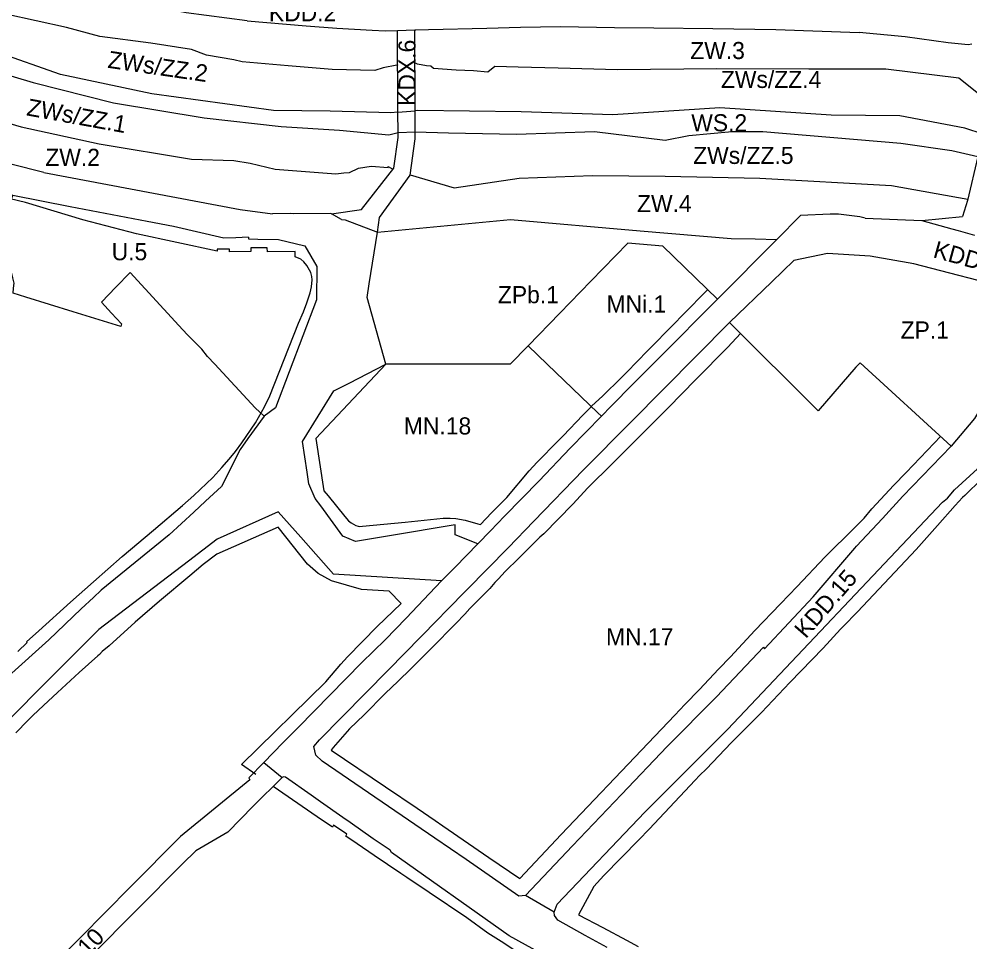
# Model space of a CAD drawing. Extents: x 7418991 to 7423142, y 5547704 to 5549547.
# Drawn here: x 7420035 to 7420312.9, y 5548281.5 to 5548551.2 of the extents above; entities that cross this region are included whole.
import ezdxf

# ---------------------------------------------------------------- set-up
doc = ezdxf.new("R2010")
doc.units = 0
for name, color, linetype in [('LIN_Linia Zabudowy Nieprzekraczalna', 7, 'Continuous'), ('LIN_linie_rozgraniczajace', 7, 'Continuous'), ('LIN_Orientacyjny przebieg terenow WS pod terenami komunikacyjnymi', 7, 'Continuous'), ('TXT_Oznaczenia_przeznaczen', 7, 'Continuous')]:
    doc.layers.add(name, color=color, linetype=linetype)

msp = doc.modelspace()

# ---------------------------------------------------------------- linework, layer by layer
at = {"layer": 'LIN_Linia Zabudowy Nieprzekraczalna'}
msp.add_line((7420172.32, 5548306.13), (7420181.35, 5548300.06), dxfattribs=at)
for points in [[(7420034.6, 5548366.36), (7420037.35, 5548369.05), (7420037.21, 5548369.21), (7420040.73, 5548372.45), (7420050.02, 5548380.77), (7420056.73, 5548386.74), (7420065.17, 5548394.09), (7420074.32, 5548401.81), (7420082.77, 5548409.02), (7420086.09, 5548411.99), (7420091.62, 5548417.27), (7420094.28, 5548420.12), (7420096.42, 5548422.55), (7420098.27, 5548424.78), (7420100.09, 5548427.35), (7420104.05, 5548433.22), (7420106.73, 5548437.9), (7420108.27, 5548441.11), (7420116.67, 5548462.31), (7420118.1, 5548465.62), (7420119.13, 5548468.25), (7420120.06, 5548471.15), (7420120.46, 5548472.96), (7420120.67, 5548475.04), (7420120.6, 5548475.97), (7420120.25, 5548477.15), (7420119.14, 5548479.15), (7420118.24, 5548480.24), (7420117.37, 5548480.99), (7420116.9, 5548481.24), (7420115.67, 5548481.73), (7420115.66, 5548483.24), (7420107.59, 5548483.15), (7420107.55, 5548484.38), (7420104.25, 5548484.33), (7420102.7, 5548484.32), (7420102.76, 5548483.24), (7420096.52, 5548483.14), (7420096.52, 5548483.96), (7420092.91, 5548483.99), (7420092.92, 5548483.37), (7420069.34, 5548488.4), (7420053.58, 5548492.52), (7420036.89, 5548497.59), (7420029.91, 5548499.2)], [(7420142.23, 5548450.36), (7420121.77, 5548428.59), (7420121.77, 5548428.59), (7420124.11, 5548413.36), (7420125.33, 5548411.91), (7420130.18, 5548405.78), (7420131.28, 5548404.6), (7420132.07, 5548404.01), (7420133.4, 5548403.21), (7420134.11, 5548402.98), (7420134.49, 5548402.93), (7420135.33, 5548402.96), (7420147.82, 5548404.19), (7420158.95, 5548405.36), (7420161.04, 5548405.38), (7420162.69, 5548405.24), (7420165.34, 5548404.74), (7420169.08, 5548403.69), (7420169.85, 5548403.53), (7420173.07, 5548406.85), (7420177.52, 5548411.39), (7420184.05, 5548419.18), (7420186.42, 5548421.66), (7420192.54, 5548427.94), (7420193.99, 5548429.38), (7420199.81, 5548435.41), (7420202.26, 5548437.95), (7420202.34, 5548438.03), (7420204.58, 5548440.12), (7420205.53, 5548441), (7420211.03, 5548446.48), (7420212.59, 5548448.05), (7420218.72, 5548454.29), (7420221.06, 5548456.67), (7420224.09, 5548459.75), (7420225.22, 5548460.91), (7420235.18, 5548470.99), (7420236.27, 5548472.16)], [(7420245.86, 5548459.33), (7420242.12, 5548455.28), (7420232.81, 5548445.85), (7420224.7, 5548437.61), (7420216.85, 5548429.65), (7420215.56, 5548428.45), (7420212.44, 5548425.28), (7420208.46, 5548421.29), (7420201.26, 5548414.16), (7420196.88, 5548409.41), (7420188.34, 5548400.8), (7420187.19, 5548399.8), (7420186.13, 5548398.69), (7420181.11, 5548393.66), (7420177.11, 5548389.72)], [(7420284.24, 5548408.09), (7420286.9, 5548410.88), (7420290.61, 5548414.84), (7420294.24, 5548418.69), (7420302.48, 5548427.22), (7420304.36, 5548429.2)], [(7420316.37, 5548416.85), (7420311.47, 5548411.98), (7420310.73, 5548411.34), (7420308.59, 5548409.07), (7420303.4, 5548403.15), (7420297.23, 5548396.17), (7420280.01, 5548377.98), (7420275.88, 5548373.7), (7420275.09, 5548372.88), (7420269.98, 5548367.33), (7420260.23, 5548357.33), (7420251.95, 5548348.56), (7420243.13, 5548339.7), (7420235.91, 5548332.11), (7420233.87, 5548330.09), (7420232.62, 5548328.74), (7420219.13, 5548314.46), (7420216.16, 5548311.33), (7420205.91, 5548300.89), (7420202.96, 5548297.7), (7420198.53, 5548289.43), (7420205.61, 5548285.67), (7420212.5, 5548282.01), (7420215.9, 5548280.19)], [(7420181.35, 5548300.06), (7420193.47, 5548312.92), (7420218.87, 5548339.54), (7420226.65, 5548347.8), (7420229.62, 5548350.91), (7420233.86, 5548355.31), (7420239.42, 5548361.21), (7420242.92, 5548364.83), (7420250.09, 5548372.52), (7420257.56, 5548380.29), (7420262.39, 5548385.33), (7420270.46, 5548393.92), (7420279.23, 5548402.63), (7420282.05, 5548405.34), (7420284.24, 5548408.09)], [(7420104.17, 5548330.46), (7420099.98, 5548333.37), (7420124.64, 5548357.54), (7420129, 5548362.69), (7420131.03, 5548364.77), (7420139.63, 5548373.63), (7420146.65, 5548380.36), (7420143.2, 5548383.97), (7420135.06, 5548384.46), (7420126.3, 5548386.98), (7420122.42, 5548389.21), (7420119.34, 5548391.92), (7420110.68, 5548402.74), (7420092.79, 5548394.8), (7420088.84, 5548391.79), (7420084.86, 5548388.5), (7420076.06, 5548381.07), (7420068.97, 5548374.91), (7420061.28, 5548368.07), (7420059.3, 5548366.33), (7420058.49, 5548365.52), (7420057.99, 5548365.06), (7420052.57, 5548360.25), (7420046.23, 5548354.41), (7420042.13, 5548350.63), (7420039.01, 5548347.62), (7420037.56, 5548346.25), (7420034.04, 5548342.63)], [(7420177.11, 5548389.72), (7420175.12, 5548387.6), (7420174.03, 5548386.5), (7420172.57, 5548384.8), (7420168.53, 5548380.7), (7420167.57, 5548379.7), (7420166.77, 5548378.98), (7420165.24, 5548377.25), (7420162.61, 5548374.6), (7420160.49, 5548372.45), (7420157.65, 5548369.45), (7420149.5, 5548361.27), (7420145.82, 5548357.74), (7420141.99, 5548354.06), (7420135.86, 5548347.87), (7420131.6, 5548343.73), (7420126.8, 5548338.28), (7420126.25, 5548337.57)], [(7420126.25, 5548337.57), (7420142.06, 5548326.8), (7420151.31, 5548320.57), (7420156.61, 5548316.94), (7420158.81, 5548315.39), (7420172.32, 5548306.13)], [(7420126.58, 5548315.07), (7420122.08, 5548318.02), (7420109.24, 5548326.94)], [(7420130.49, 5548312.44), (7420130.83, 5548312.98), (7420126.89, 5548315.57), (7420126.58, 5548315.07)], [(7420171.96, 5548284.09), (7420165.88, 5548288.49), (7420154.89, 5548295.92), (7420148.36, 5548300.37), (7420146.54, 5548301.51), (7420138.81, 5548306.73), (7420133.83, 5548310.12), (7420130.49, 5548312.44)], [(7420237.78, 5548247.63), (7420224.14, 5548255.15), (7420214.05, 5548260.52), (7420213.07, 5548261.03), (7420207.42, 5548264.13), (7420205.33, 5548265.07), (7420204.63, 5548265.38), (7420201.48, 5548267.03), (7420194.08, 5548270.96), (7420191.28, 5548272.61), (7420181.08, 5548278.29), (7420180.07, 5548278.89), (7420179.13, 5548279.52), (7420176.65, 5548281.16), (7420171.96, 5548284.09)]]:
    msp.add_lwpolyline(points, dxfattribs=at)
at = {"layer": 'LIN_linie_rozgraniczajace'}
for p, q in [((7420048.85, 5548548.76), (7420031.14, 5548552.63)), ((7420058.61, 5548546.09), (7420048.85, 5548548.76)), ((7420073.48, 5548544.19), (7420058.61, 5548546.09)), ((7420256.22, 5548548.13), (7420280.58, 5548547.3)), ((7420085.39, 5548542.31), (7420073.48, 5548544.19)), ((7420089.74, 5548540.69), (7420085.39, 5548542.31)), ((7420097.8, 5548539.27), (7420089.74, 5548540.69)), ((7420100.24, 5548538.67), (7420097.8, 5548539.27)), ((7420113.66, 5548537.58), (7420100.24, 5548538.67)), ((7420126.47, 5548536.45), (7420113.66, 5548537.58)), ((7420145.45, 5548537.7), (7420141.43, 5548536.93)), ((7420145.67, 5548537.86), (7420145.45, 5548537.7)), ((7420150.83, 5548538.29), (7420150.67, 5548538.31)), ((7420151.45, 5548538.02), (7420150.83, 5548538.29)), ((7420154.1, 5548537.5), (7420151.45, 5548538.02)), ((7420155.31, 5548537.39), (7420154.1, 5548537.5)), ((7420156.16, 5548536.78), (7420155.31, 5548537.39)), ((7420174.09, 5548537.34), (7420171.99, 5548535.73)), ((7420180.9, 5548537.15), (7420174.09, 5548537.34)), ((7420192.52, 5548536.87), (7420180.9, 5548537.15)), ((7420138.96, 5548536.2), (7420126.47, 5548536.45)), ((7420141.43, 5548536.93), (7420138.96, 5548536.2)), ((7420162.74, 5548536.27), (7420156.16, 5548536.78)), ((7420167.79, 5548536.06), (7420162.74, 5548536.27)), ((7420171.99, 5548535.73), (7420167.79, 5548536.06)), ((7420209.87, 5548536.39), (7420192.52, 5548536.87)), ((7420238.96, 5548536.67), (7420209.87, 5548536.39)), ((7420265.81, 5548536.6), (7420238.96, 5548536.67)), ((7420288.31, 5548536.52), (7420265.81, 5548536.6)), ((7420309.63, 5548533.94), (7420288.31, 5548536.52)), ((7420317.9, 5548527.42), (7420309.63, 5548533.94)), ((7420016.69, 5548525.28), (7420035.64, 5548519.71)), ((7420035.64, 5548519.71), (7420058.42, 5548514.75)), ((7420058.42, 5548514.75), (7420085.38, 5548510.26)), ((7420085.38, 5548510.26), (7420097.72, 5548509.85)), ((7420097.72, 5548509.85), (7420102.55, 5548509.13)), ((7420042.19, 5548506.4), (7420032.55, 5548508.76)), ((7420102.55, 5548509.13), (7420109.87, 5548507.31)), ((7420109.87, 5548507.31), (7420127.57, 5548505.95)), ((7420131.58, 5548506.33), (7420134.23, 5548507.65)), ((7420134.23, 5548507.65), (7420137.95, 5548508.21)), ((7420137.95, 5548508.21), (7420142.88, 5548507.82)), ((7420142.88, 5548507.82), (7420142.9, 5548508.07)), ((7420142.9, 5548508.07), (7420144.28, 5548507.29)), ((7420127.57, 5548505.95), (7420129.95, 5548506.22)), ((7420129.95, 5548506.22), (7420131.58, 5548506.33)), ((7420149.33, 5548505.72), (7420162.17, 5548501.92)), ((7420162.17, 5548501.92), (7420181.12, 5548504.67)), ((7420181.12, 5548504.67), (7420202.56, 5548505.44)), ((7420202.56, 5548505.44), (7420223.82, 5548505.27)), ((7420223.82, 5548505.27), (7420251.53, 5548504.67)), ((7420251.53, 5548504.67), (7420289.97, 5548502.56)), ((7420289.97, 5548502.56), (7420312.35, 5548498.6)), ((7420298.88, 5548492.32), (7420310.79, 5548493.54)), ((7420223.18, 5548484.8), (7420212.97, 5548485.68)), ((7420223.18, 5548484.8), (7420239.14, 5548469.39)), ((7420104, 5548437.58), (7420106.67, 5548435.18)), ((7420106.67, 5548435.18), (7420101.88, 5548428.64)), ((7420158.48, 5548387.04), (7420154.98, 5548383.32)), ((7420106.51, 5548333.93), (7420111.91, 5548329.57)), ((7420178.28, 5548283.31), (7420143.89, 5548307.63))]:
    msp.add_line(p, q, dxfattribs=at)
for points in [[(7420073.76, 5548529.37), (7420047.08, 5548535), (7420028.23, 5548541.62), (7420003.67, 5548548.84), (7419981.84, 5548558.41), (7419945.29, 5548578.67), (7419918.24, 5548595.43), (7419880.08, 5548624.72)], [(7420101.65, 5548550.71), (7420083.87, 5548553.03), (7420081.26, 5548553.53)], [(7420101.65, 5548550.71), (7420118.9, 5548549.2), (7420127.9, 5548548.5), (7420138.22, 5548548), (7420141.97, 5548547.78), (7420145.63, 5548547.9), (7420150.63, 5548548.02), (7420150.98, 5548548.03), (7420154.65, 5548548.14)], [(7420154.65, 5548548.14), (7420171.74, 5548548.5), (7420181.51, 5548548.83), (7420193.29, 5548549.01), (7420209.01, 5548548.75), (7420220.52, 5548548.6), (7420237.78, 5548548.43), (7420256.22, 5548548.13)], [(7420126.35, 5548494.25), (7420135.04, 5548495.54), (7420144.54, 5548507.63), (7420145.75, 5548516.54), (7420145.75, 5548518.05), (7420145.72, 5548523.96), (7420145.63, 5548547.9)], [(7420139.8, 5548488.92), (7420140.31, 5548493.18), (7420149.31, 5548505.61), (7420150.75, 5548516.21), (7420150.75, 5548518.2), (7420150.72, 5548524.39), (7420150.63, 5548548.02)], [(7420313.51, 5548543.89), (7420312.43, 5548543.71), (7420306.53, 5548544.23), (7420293.98, 5548546.02), (7420280.58, 5548547.3)], [(7420013.19, 5548540.38), (7420039.08, 5548532.71), (7420062.63, 5548526.75), (7420089.13, 5548522.35), (7420111.61, 5548519.84)], [(7420322.75, 5548541.8), (7420319.18, 5548527.65), (7420316.8, 5548517.55), (7420315.27, 5548511.05), (7420312.24, 5548498.16), (7420310.79, 5548493.54)], [(7420145.72, 5548523.96), (7420143.7, 5548523.79), (7420125.92, 5548524.26), (7420109.34, 5548524.44), (7420073.76, 5548529.37)], [(7420316.8, 5548517.55), (7420311.39, 5548519.28), (7420292.38, 5548522.88), (7420272.31, 5548523.1), (7420239.8, 5548525.23), (7420208.56, 5548523.24), (7420181.75, 5548524.11), (7420151.53, 5548524.46), (7420150.72, 5548524.39)], [(7420111.61, 5548519.84), (7420128.64, 5548518.76), (7420143.04, 5548517.32), (7420145.75, 5548518.05)], [(7420150.75, 5548518.2), (7420160.53, 5548517.95), (7420180.36, 5548517.54)], [(7420180.36, 5548517.54), (7420203.18, 5548518.38), (7420223.79, 5548515.78), (7420230.78, 5548517.2), (7420243.46, 5548518.36), (7420252.36, 5548518.3), (7420292.72, 5548514.97), (7420307.65, 5548512.78), (7420315.27, 5548511.05)], [(7420042.19, 5548506.4), (7420099.65, 5548495.51), (7420109.11, 5548494.27)], [(7420102.05, 5548487.44), (7420098.3, 5548487.29), (7420094.85, 5548487.14), (7420080.12, 5548490.58), (7420072.4, 5548492), (7420049.93, 5548496.37), (7420033.21, 5548499.61), (7420032.5, 5548499.98), (7420031.64, 5548500.52), (7420028.77, 5548502.25), (7420028.02, 5548502.66)], [(7420059.04, 5548468.48), (7420061.98, 5548465.29), (7420064.91, 5548462.09), (7420064.8, 5548461.72), (7420064.7, 5548461.35), (7420050.83, 5548465.66), (7420036.97, 5548469.97), (7420033.31, 5548471.11), (7420033.41, 5548472.58), (7420033.51, 5548474.05), (7420033.15, 5548475.53), (7420032.78, 5548477), (7420030.7, 5548480.41), (7420028.62, 5548483.81), (7420027.7, 5548485.84), (7420030.46, 5548492.73), (7420033.21, 5548499.61)], [(7420129.19, 5548492.6), (7420126.35, 5548494.25), (7420126.13, 5548494.38), (7420115.27, 5548494.26), (7420114.31, 5548494.39), (7420109.11, 5548494.27)], [(7420129.19, 5548492.6), (7420130.34, 5548492.53), (7420139.8, 5548488.92)], [(7420139.8, 5548488.92), (7420178.62, 5548492.62), (7420216.55, 5548489.36), (7420243.12, 5548487.07), (7420250.16, 5548486.93), (7420256.45, 5548486.81)], [(7420256.45, 5548486.81), (7420263.44, 5548493.84)], [(7420282.26, 5548493.03), (7420280.7, 5548493.36), (7420274.48, 5548494.15), (7420272.04, 5548494.22), (7420263.44, 5548493.84)], [(7420282.26, 5548493.03), (7420298.88, 5548492.32), (7420307.66, 5548489.91), (7420309.48, 5548489.39), (7420314.29, 5548488.01)], [(7420102.05, 5548487.44), (7420102.07, 5548486.98), (7420104.77, 5548486.92), (7420110.82, 5548486.78), (7420118.5, 5548484.88), (7420122.02, 5548478.85), (7420121.94, 5548469.19), (7420109.97, 5548437.61), (7420106.67, 5548435.18)], [(7420205.18, 5548435.14), (7420204.13, 5548436.15), (7420189.35, 5548450.34), (7420183.76, 5548455.71), (7420178.53, 5548450.35), (7420142.23, 5548450.36), (7420136.72, 5548469.87), (7420137.36, 5548473.85), (7420139.8, 5548488.92)], [(7420183.76, 5548455.71), (7420193.08, 5548465.27), (7420202.13, 5548474.56), (7420212.97, 5548485.68)], [(7420256.45, 5548486.81), (7420239.14, 5548469.39), (7420237.44, 5548467.68)], [(7420330.47, 5548470.16), (7420327.57, 5548471.58), (7420325.85, 5548472.03), (7420296.52, 5548479.65), (7420283.8, 5548481.93), (7420271.25, 5548482.64), (7420261.45, 5548480.64), (7420254.99, 5548474.39), (7420242.67, 5548462.51)], [(7420104, 5548437.58), (7420092.17, 5548450.39), (7420090.1, 5548452.63), (7420088.39, 5548454.7), (7420084.13, 5548458.97), (7420081.69, 5548461.62), (7420067.48, 5548477.11), (7420063.26, 5548472.8), (7420059.04, 5548468.48)], [(7420237.44, 5548467.68), (7420223.7, 5548453.86), (7420214.51, 5548444.61), (7420208.04, 5548438.1), (7420205.18, 5548435.14), (7420196.11, 5548425.75), (7420186.97, 5548416.28), (7420176.92, 5548405.88), (7420172.8, 5548401.66), (7420169.05, 5548397.82), (7420162.42, 5548391.04), (7420158.48, 5548387.04)], [(7420191.37, 5548290.16), (7420192.24, 5548292.52), (7420217.89, 5548319.42), (7420242.02, 5548343.53), (7420304.85, 5548409.98), (7420306.38, 5548411.15), (7420308.4, 5548413.59), (7420315.16, 5548419.76), (7420321.32, 5548427.36), (7420324.56, 5548432.31), (7420326.3, 5548434.96), (7420331.4, 5548445.41), (7420341.19, 5548465.32), (7420343.42, 5548470.14)], [(7420328.33, 5548465.17), (7420322.86, 5548452.47), (7420317.05, 5548439.23), (7420314.25, 5548434.48), (7420307.45, 5548426.37), (7420280.85, 5548450.7), (7420279.61, 5548449.42), (7420268.58, 5548436.74), (7420242.67, 5548462.51)], [(7420121.18, 5548338.57), (7420122.8, 5548340.59), (7420142.89, 5548360.94), (7420157.33, 5548375.66), (7420159.94, 5548378.32), (7420171.94, 5548390.52), (7420177.92, 5548396.69), (7420185.49, 5548404.49), (7420200.01, 5548419.46), (7420213.82, 5548433.39), (7420242.67, 5548462.51)], [(7420169.05, 5548397.82), (7420162.46, 5548400.47), (7420162.47, 5548403.41), (7420143.24, 5548400.2), (7420133.31, 5548398.54), (7420129.65, 5548400.06), (7420123.17, 5548408.9), (7420121.55, 5548411.12), (7420119.71, 5548415.42), (7420119.23, 5548418.77), (7420117.85, 5548427.78), (7420127.01, 5548442.57), (7420131.43, 5548444.83), (7420142.23, 5548450.36)], [(7420101.88, 5548428.64), (7420099.58, 5548425.39), (7420094.14, 5548414.63), (7420089.44, 5548410.27), (7420086.07, 5548407.13), (7420078.82, 5548400.46), (7420059, 5548384.29), (7420056.7, 5548382.17), (7420053.1, 5548378.85), (7420043.71, 5548369.75), (7420031.87, 5548359.17), (7420023.15, 5548351.99), (7420013.93, 5548342.29), (7420003.1, 5548330.8)], [(7420183, 5548295.08), (7420196.74, 5548309.57), (7420211.1, 5548324.59), (7420224.43, 5548338.64), (7420238.85, 5548353.12), (7420252.54, 5548367.59), (7420252.91, 5548367.19), (7420267.07, 5548382.36), (7420279.28, 5548396.58), (7420279.8, 5548397.13), (7420287.36, 5548405.2), (7420293.34, 5548411.78), (7420307.45, 5548426.37)], [(7420158.48, 5548387.04), (7420126.91, 5548388.97), (7420117.31, 5548399.77), (7420110.75, 5548407.15), (7420092.89, 5548399.22), (7420084.49, 5548392.8), (7420058.27, 5548372.81), (7420044.54, 5548359.06), (7420016.1, 5548330.54), (7420017.89, 5548328.64), (7419997.32, 5548306.91), (7419972.24, 5548279.73), (7419955.89, 5548261.61), (7419938.28, 5548242.93), (7419917.3, 5548219.73), (7419911.59, 5548213.29), (7419908.65, 5548209.49)], [(7420154.98, 5548383.32), (7420148.16, 5548376.08), (7420141.98, 5548369.82), (7420135.19, 5548363.15), (7420116.58, 5548344.18), (7420112.13, 5548339.67), (7420106.51, 5548333.93)], [(7420206.86, 5548279.87), (7420200.41, 5548283.37), (7420192.46, 5548287.89), (7420191.53, 5548289.19), (7420191.37, 5548290.16), (7420183, 5548295.08), (7420181.1, 5548294.91), (7420165.65, 5548305.61), (7420156.47, 5548311.85), (7420123.56, 5548334.3), (7420121.71, 5548336.11), (7420121.18, 5548338.57)], [(7420106.51, 5548333.93), (7420102.14, 5548329.46), (7420102.47, 5548328.89)], [(7420111.92, 5548329.58), (7420111.91, 5548329.57), (7420103.38, 5548321.17), (7420095.97, 5548313.59), (7420086.63, 5548308.14), (7420082.78, 5548304.28), (7420069.37, 5548290.83), (7420055.95, 5548277.38), (7420050.3, 5548271.71), (7420050.35, 5548267.51), (7420043.99, 5548261.14), (7420039.67, 5548265.29), (7420037.82, 5548266.71), (7420035.28, 5548269.12), (7420041.67, 5548275.57), (7420045.88, 5548275.57), (7420052.97, 5548282.76), (7420067.6, 5548297.55), (7420082.18, 5548312.32)], [(7420102.47, 5548328.89), (7420082.18, 5548312.32)], [(7420143.89, 5548307.63), (7420143.48, 5548308.28), (7420138.53, 5548311.65), (7420131.76, 5548316.37), (7420129.64, 5548317.85), (7420123.13, 5548322.46), (7420120.34, 5548324.4), (7420112.83, 5548329.69), (7420112.28, 5548329.71), (7420111.92, 5548329.58)], [(7420212.54, 5548264.35), (7420178.28, 5548283.31)]]:
    msp.add_lwpolyline(points, dxfattribs=at)
at = {"layer": 'LIN_Orientacyjny przebieg terenow WS pod terenami komunikacyjnymi'}
for p, q in [((7420145.72, 5548523.96), (7420150.72, 5548524.39)), ((7420145.75, 5548518.05), (7420150.75, 5548518.2))]:
    msp.add_line(p, q, dxfattribs=at)

# ---------------------------------------------------------------- texts
at = {"layer": 'TXT_Oznaczenia_przeznaczen'}
for s, p in [('KDD.2', (7420108.02, 5548550.54)), ('ZW.3', (7420231.17, 5548539.51)), ('ZWs/ZZ.4', (7420240.13, 5548531.07)), ('ZW.2', (7420042.66, 5548508.28)), ('ZWs/ZZ.5', (7420232.02, 5548508.86)), ('ZW.4', (7420215.62, 5548494.77)), ('U.5', (7420062.05, 5548480.71)), ('ZPb.1', (7420174.94, 5548468.16)), ('MNi.1', (7420206.7, 5548465.43)), ('ZP.1', (7420292.66, 5548457.83)), ('MN.18', (7420147.45, 5548429.8)), ('MN.17', (7420206.55, 5548368.19))]:
    msp.add_text(s, height=5, dxfattribs=at).set_placement(p)
for s, rotation, p in [('KDX.6', 90.0064, (7420150.89, 5548525.84)), ('ZWs/ZZ.2', 351.7365, (7420060.7, 5548536.99)), ('ZWs/ZZ.1', 349.7336, (7420036.98, 5548523.08)), ('WS.2', 0.0064, (7420231.46, 5548518.38)), ('KDD.14', 344.6018, (7420301.88, 5548481.63)), ('KDD.15', 49.0074, (7420264.94, 5548369.91)), ('KDW.10', 46.655, (7420043.21, 5548264.47))]:
    msp.add_text(s, height=5, rotation=rotation, dxfattribs=at).set_placement(p)

doc.saveas('drawing.dxf')
